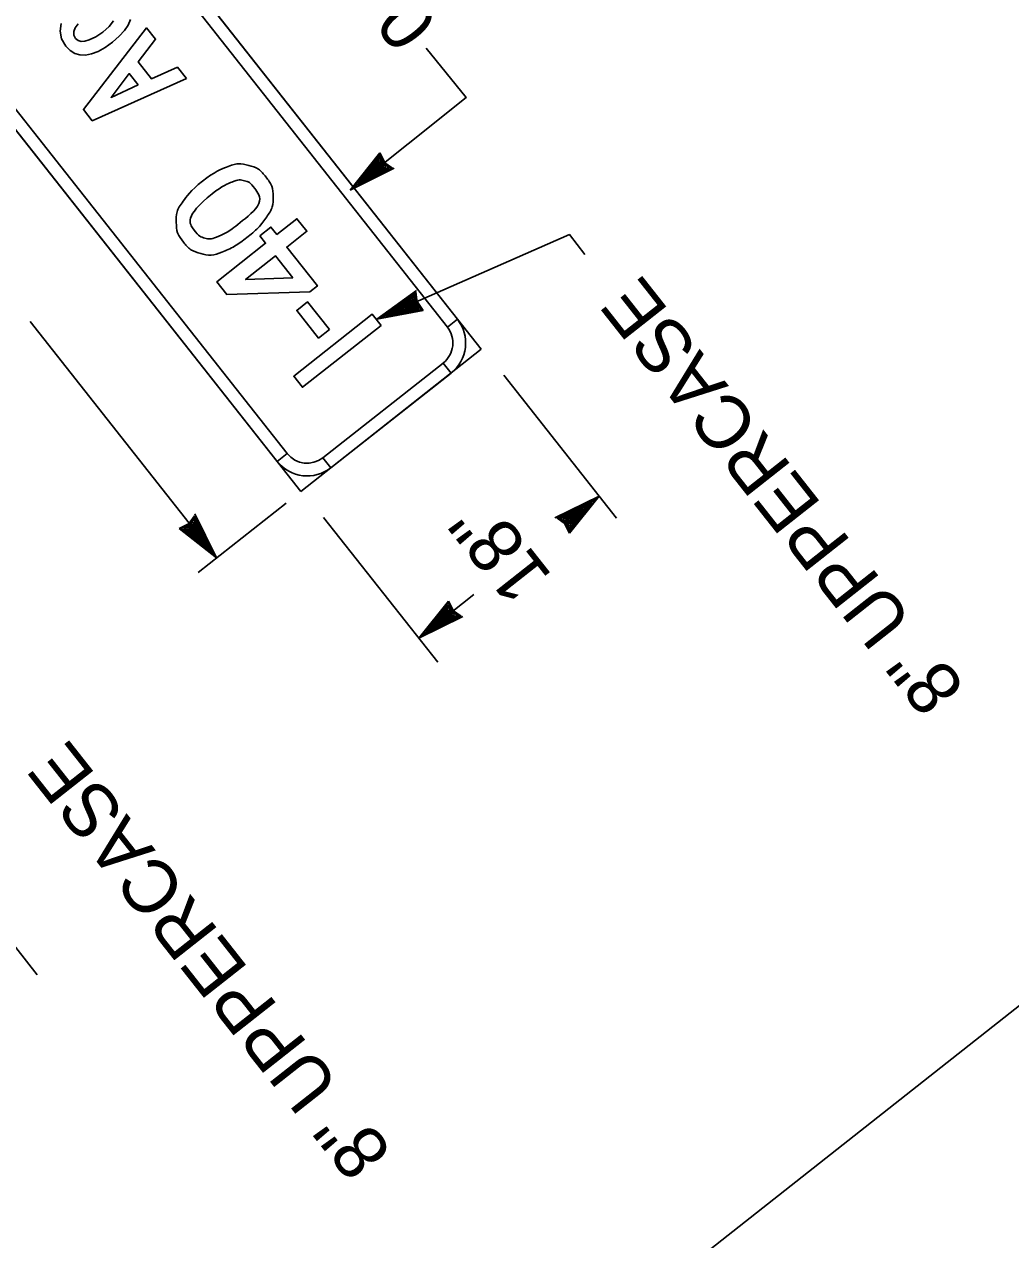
# Model space of a CAD drawing. Extents: x 672126 to 673696, y 1673540 to 1674900.
# Drawn here: x 672298.2 to 672375.5, y 1674587.2 to 1674682.5 of the extents above; entities that cross this region are included whole.
import ezdxf

# ---------------------------------------------------------------- set-up
doc = ezdxf.new("R2010")
doc.units = 0
doc.layers.add('C-ANNO-SYMB', color=7, linetype='Continuous')
doc.layers.add('Level 1', color=7, linetype='Continuous')

msp = doc.modelspace()

# ---------------------------------------------------------------- linework, layer by layer
at = {"layer": 'C-ANNO-SYMB'}
for p, q in [((672289.398, 1674713.6), (672333.973, 1674657.057)), ((672275.262, 1674702.456), (672319.838, 1674645.914)), ((672332.116, 1674659.413), (672331.331, 1674658.794)), ((672319.838, 1674645.914), (672333.973, 1674657.057)), ((672330.998, 1674655.985), (672331.617, 1674655.2)), ((672318.766, 1674648.889), (672317.98, 1674648.27)), ((672322.194, 1674647.771), (672321.575, 1674648.556))]:
    msp.add_line(p, q, dxfattribs=at)
for points in [[(672331.331, 1674658.794), (672290.47, 1674710.625), (672291.255, 1674711.244), (672332.116, 1674659.413), (672331.331, 1674658.794), (672331.331, 1674658.794)], [(672277.905, 1674700.719), (672318.766, 1674648.889), (672317.98, 1674648.27), (672277.12, 1674700.1), (672277.905, 1674700.719), (672277.905, 1674700.719)], [(672322.081, 1674658.601), (672320.367, 1674660.775), (672319.521, 1674660.108), (672321.235, 1674657.934)], [(672326.125, 1674658.937), (672325.439, 1674659.807), (672319.278, 1674654.949), (672319.963, 1674654.08)], [(672321.575, 1674648.556), (672330.998, 1674655.985), (672331.617, 1674655.2), (672322.194, 1674647.771), (672321.575, 1674648.556), (672321.575, 1674648.556)]]:
    msp.add_lwpolyline(points, close=True, dxfattribs=at)
for points in [[(672301.055, 1674682.604), (672300.962, 1674682.007), (672301.088, 1674681.405), (672301.42, 1674680.832), (672301.751, 1674680.489), (672302.116, 1674680.26), (672302.519, 1674680.137), (672302.955, 1674680.123), (672303.432, 1674680.217), (672303.94, 1674680.419), (672304.487, 1674680.731), (672305.069, 1674681.15), (672305.591, 1674681.602), (672306.002, 1674682.045), (672306.303, 1674682.481), (672306.489, 1674682.909)], [(672305.163, 1674682.816), (672304.8, 1674682.376), (672304.305, 1674681.937), (672303.764, 1674681.563), (672303.245, 1674681.312), (672302.903, 1674681.211), (672302.61, 1674681.198), (672302.373, 1674681.27), (672302.183, 1674681.433), (672302.05, 1674681.69), (672302.037, 1674681.967), (672302.146, 1674682.268), (672302.371, 1674682.588)], [(672310.87, 1674678.287), (672310.165, 1674679.181), (672308.14, 1674678.261), (672307.092, 1674679.59), (672308.445, 1674681.364), (672307.735, 1674682.264), (672302.798, 1674675.853), (672303.485, 1674674.983), (672310.87, 1674678.287)], [(672307.092, 1674677.787), (672304.96, 1674676.811), (672306.387, 1674678.682), (672307.092, 1674677.787)], [(672316.619, 1674665.954), (672317.499, 1674666.647), (672317.96, 1674666.063), (672319.531, 1674667.301), (672320.31, 1674666.313), (672318.739, 1674665.075), (672321.136, 1674662.033), (672320.546, 1674661.567), (672314.025, 1674661.359), (672313.246, 1674662.347), (672317.08, 1674665.369), (672316.619, 1674665.954)], [(672319.221, 1674662.653), (672317.859, 1674664.381), (672315.509, 1674662.528), (672319.221, 1674662.653)]]:
    msp.add_lwpolyline(points, dxfattribs=at)
for centre, radius, start, end in [((672329.76, 1674657.556), 3, 308.25039, 38.2506), ((672329.76, 1674657.556), 2, 308.25039, 38.2506), ((672320.336, 1674650.127), 2, 218.25075, 308.25039), ((672320.336, 1674650.127), 3, 218.25075, 308.25039)]:
    msp.add_arc(centre, radius, start, end, dxfattribs=at)
for points in [[(672312.123, 1674670.234), (672313.085, 1674670.992), (672314.129, 1674671.387), (672314.923, 1674671.698), (672315.757, 1674671.48), (672316.563, 1674671.259), (672317.104, 1674670.574), (672317.644, 1674669.889), (672317.664, 1674669.048), (672317.686, 1674668.193), (672317.186, 1674667.484), (672316.539, 1674666.559), (672315.603, 1674665.821), (672314.667, 1674665.083), (672313.616, 1674664.67), (672312.805, 1674664.355), (672311.99, 1674664.575), (672311.166, 1674664.792), (672310.631, 1674665.471), (672310.096, 1674666.15), (672310.076, 1674667.002), (672310.048, 1674667.865), (672310.535, 1674668.565), (672311.181, 1674669.491), (672312.123, 1674670.234)], [(672312.894, 1674669.256), (672310.638, 1674667.478), (672311.605, 1674666.252), (672311.887, 1674665.894), (672312.307, 1674665.781), (672312.727, 1674665.669), (672313.15, 1674665.83), (672314.034, 1674666.169), (672314.832, 1674666.799), (672317.088, 1674668.577), (672316.117, 1674669.809), (672315.834, 1674670.168), (672315.42, 1674670.279), (672315.006, 1674670.391), (672314.582, 1674670.23), (672313.693, 1674669.886), (672312.894, 1674669.256)]]:
    msp.add_open_spline(points, degree=3, dxfattribs=at)
at = {"layer": 'Level 1'}
for p, q in [((672525.22, 1674723.119), (672265.685, 1674518.515)), ((672323.7, 1674669.545), (672326.02, 1674672.456)), ((672323.918, 1674669.782), (672326.002, 1674672.307)), ((672326.002, 1674672.307), (672326.343, 1674671.742)), ((672326.02, 1674672.456), (672326.412, 1674671.696)), ((672324.269, 1674670.057), (672325.999, 1674672.139)), ((672324.488, 1674670.157), (672326.042, 1674671.873)), ((672324.559, 1674670.281), (672326.001, 1674672.007)), ((672324.993, 1674670.621), (672325.987, 1674671.729)), ((672326.503, 1674671.368), (672324.993, 1674670.621)), ((672325.38, 1674670.89), (672325.951, 1674671.602)), ((672326.34, 1674671.407), (672325.38, 1674670.89)), ((672326.045, 1674671.742), (672325.54, 1674670.983)), ((672325.716, 1674671.185), (672325.981, 1674671.525)), ((672326.233, 1674671.456), (672325.716, 1674671.185)), ((672325.951, 1674671.602), (672326.233, 1674671.456)), ((672325.981, 1674671.525), (672326.064, 1674671.46)), ((672325.987, 1674671.729), (672326.34, 1674671.407)), ((672325.999, 1674672.139), (672326.137, 1674671.879)), ((672326.001, 1674672.007), (672326.682, 1674671.309)), ((672326.042, 1674671.873), (672326.503, 1674671.368)), ((672326.421, 1674671.471), (672326.045, 1674671.742)), ((672326.064, 1674671.46), (672326.421, 1674671.471)), ((672326.137, 1674671.879), (672326.682, 1674671.309)), ((672326.343, 1674671.742), (672327.014, 1674671.269)), ((672326.412, 1674671.696), (672326.654, 1674671.387)), ((672326.654, 1674671.387), (672326.969, 1674671.199)), ((672327.161, 1674671.251), (672323.7, 1674669.545)), ((672326.803, 1674671.237), (672323.96, 1674669.813)), ((672326.969, 1674671.199), (672324.121, 1674669.905)), ((672326.682, 1674671.309), (672324.488, 1674670.157)), ((672326.682, 1674671.309), (672324.559, 1674670.281)), ((672325.54, 1674670.983), (672325.286, 1674670.883)), ((672327.014, 1674671.269), (672326.795, 1674671.333)), ((672326.795, 1674671.333), (672326.803, 1674671.237)), ((672328.904, 1674661.681), (672325.785, 1674659.411)), ((672328.725, 1674661.371), (672326.142, 1674659.516)), ((672328.769, 1674661.535), (672326.299, 1674659.616)), ((672328.733, 1674661.23), (672326.693, 1674659.824)), ((672328.733, 1674661.23), (672326.835, 1674659.829)), ((672328.701, 1674661.044), (672327.338, 1674660.055)), ((672328.661, 1674660.882), (672327.756, 1674660.273)), ((672328.579, 1674660.612), (672328.755, 1674660.924)), ((672328.781, 1674660.419), (672328.661, 1674660.882)), ((672328.935, 1674660.401), (672328.701, 1674661.044)), ((672328.806, 1674661.319), (672328.725, 1674661.371)), ((672328.984, 1674660.483), (672328.733, 1674661.23)), ((672329.034, 1674660.302), (672328.733, 1674661.23)), ((672328.755, 1674660.924), (672328.82, 1674660.465)), ((672328.789, 1674661.169), (672328.769, 1674661.535)), ((672328.95, 1674660.811), (672328.789, 1674661.169)), ((672328.852, 1674661.542), (672328.806, 1674661.319)), ((672328.958, 1674660.728), (672328.852, 1674661.542)), ((672325.785, 1674659.411), (672329.44, 1674660.111)), ((672326.095, 1674659.494), (672329.3, 1674660.163)), ((672326.265, 1674659.686), (672327.013, 1674660.196)), ((672326.502, 1674659.676), (672329.149, 1674660.239)), ((672327.013, 1674660.196), (672326.502, 1674659.676)), ((672326.693, 1674659.824), (672328.935, 1674660.401)), ((672326.835, 1674659.829), (672329.034, 1674660.302)), ((672327.23, 1674660.035), (672327.617, 1674660.324)), ((672327.706, 1674660.193), (672327.23, 1674660.035)), ((672327.338, 1674660.055), (672328.781, 1674660.419)), ((672327.913, 1674660.37), (672327.706, 1674660.193)), ((672327.756, 1674660.273), (672328.652, 1674660.447)), ((672328.82, 1674660.465), (672327.913, 1674660.37)), ((672328.654, 1674660.764), (672328.174, 1674660.432)), ((672328.174, 1674660.432), (672328.598, 1674660.509)), ((672328.598, 1674660.509), (672328.579, 1674660.612)), ((672328.652, 1674660.447), (672328.654, 1674660.764)), ((672329.44, 1674660.111), (672328.95, 1674660.811)), ((672329.3, 1674660.163), (672328.958, 1674660.728)), ((672329.149, 1674660.239), (672328.984, 1674660.483)), ((672313.221, 1674640.698), (672298.606, 1674659.236)), ((672326.299, 1674659.616), (672326.095, 1674659.494)), ((672326.142, 1674659.516), (672326.265, 1674659.686)), ((672335.76, 1674655.02), (672344.589, 1674643.821)), ((672318.681, 1674645.002), (672311.777, 1674639.559)), ((672339.76, 1674643.852), (672343.221, 1674645.556)), ((672339.952, 1674643.904), (672342.801, 1674645.196)), ((672340.118, 1674643.866), (672342.962, 1674645.288)), ((672340.239, 1674643.794), (672342.433, 1674644.944)), ((672340.239, 1674643.794), (672342.362, 1674644.821)), ((672342.433, 1674644.944), (672340.878, 1674643.229)), ((672343.221, 1674645.556), (672340.9, 1674642.647)), ((672343.004, 1674645.32), (672340.918, 1674642.796)), ((672342.362, 1674644.821), (672340.919, 1674643.095)), ((672342.652, 1674645.044), (672340.921, 1674642.964)), ((672342.754, 1674645.259), (672341.955, 1674644.834)), ((672341.955, 1674644.834), (672342.652, 1674645.044)), ((672342.962, 1674645.288), (672342.754, 1674645.259)), ((672342.801, 1674645.196), (672343.004, 1674645.32)), ((672311.027, 1674643.342), (672311.5, 1674644.012)), ((672311.382, 1674643.653), (672311.57, 1674643.967)), ((672311.5, 1674644.012), (672311.436, 1674643.793)), ((672311.436, 1674643.793), (672311.532, 1674643.801)), ((672311.518, 1674644.159), (672313.221, 1674640.698)), ((672311.532, 1674643.801), (672312.954, 1674640.957)), ((672311.57, 1674643.967), (672312.862, 1674641.118)), ((672321.624, 1674643.876), (672330.58, 1674632.516)), ((672340.577, 1674643.361), (672339.907, 1674643.834)), ((672339.907, 1674643.834), (672340.126, 1674643.771)), ((672340.266, 1674643.716), (672339.952, 1674643.904)), ((672340.126, 1674643.771), (672340.118, 1674643.866)), ((672340.783, 1674643.224), (672340.239, 1674643.794)), ((672340.919, 1674643.095), (672340.239, 1674643.794)), ((672340.508, 1674643.407), (672340.266, 1674643.716)), ((672340.418, 1674643.735), (672341.928, 1674644.481)), ((672340.878, 1674643.229), (672340.418, 1674643.735)), ((672340.58, 1674643.696), (672341.541, 1674644.212)), ((672340.688, 1674643.646), (672341.205, 1674643.917)), ((672340.875, 1674643.361), (672341.381, 1674644.119)), ((672341.928, 1674644.481), (672340.934, 1674643.373)), ((672341.205, 1674643.917), (672340.939, 1674643.577)), ((672341.541, 1674644.212), (672340.969, 1674643.501)), ((672341.381, 1674644.119), (672341.634, 1674644.219)), ((672341.996, 1674644.567), (672341.56, 1674644.359)), ((672341.634, 1674644.219), (672341.996, 1674644.567)), ((672310.313, 1674643.019), (672311.072, 1674643.411)), ((672313.221, 1674640.698), (672310.313, 1674643.019)), ((672310.461, 1674643.001), (672311.027, 1674643.342)), ((672312.985, 1674640.915), (672310.461, 1674643.001)), ((672310.63, 1674642.998), (672310.89, 1674643.136)), ((672312.71, 1674641.267), (672310.63, 1674642.998)), ((672310.761, 1674643), (672311.46, 1674643.68)), ((672312.486, 1674641.557), (672310.761, 1674643)), ((672310.89, 1674643.136), (672311.46, 1674643.68)), ((672310.895, 1674643.041), (672311.401, 1674643.501)), ((672312.61, 1674641.486), (672310.895, 1674643.041)), ((672311.298, 1674643.42), (672311.027, 1674643.044)), ((672311.027, 1674643.044), (672311.785, 1674642.538)), ((672311.039, 1674642.985), (672311.361, 1674643.339)), ((672312.147, 1674641.991), (672311.039, 1674642.985)), ((672311.072, 1674643.411), (672311.382, 1674643.653)), ((672311.166, 1674642.95), (672311.312, 1674643.231)), ((672311.878, 1674642.378), (672311.166, 1674642.95)), ((672311.243, 1674642.98), (672311.308, 1674643.062)), ((672311.583, 1674642.714), (672311.243, 1674642.98)), ((672311.308, 1674643.062), (672311.298, 1674643.42)), ((672311.312, 1674643.231), (672311.583, 1674642.714)), ((672311.361, 1674643.339), (672311.878, 1674642.378)), ((672311.401, 1674643.501), (672312.147, 1674641.991)), ((672311.46, 1674643.68), (672312.486, 1674641.557)), ((672311.46, 1674643.68), (672312.61, 1674641.486)), ((672340.857, 1674643.643), (672340.499, 1674643.632)), ((672340.499, 1674643.632), (672340.875, 1674643.361)), ((672340.9, 1674642.647), (672340.508, 1674643.407)), ((672340.918, 1674642.796), (672340.577, 1674643.361)), ((672340.934, 1674643.373), (672340.58, 1674643.696)), ((672340.969, 1674643.501), (672340.688, 1674643.646)), ((672340.921, 1674642.964), (672340.783, 1674643.224)), ((672340.939, 1674643.577), (672340.857, 1674643.643)), ((672311.785, 1674642.538), (672311.885, 1674642.285)), ((672311.885, 1674642.285), (672312.233, 1674641.923)), ((672312.233, 1674641.923), (672312.025, 1674642.359)), ((672312.924, 1674641.165), (672312.499, 1674641.964)), ((672312.499, 1674641.964), (672312.71, 1674641.267)), ((672312.862, 1674641.118), (672312.985, 1674640.915)), ((672312.954, 1674640.957), (672312.924, 1674641.165)), ((672329.086, 1674634.412), (672333.411, 1674637.822)), ((672329.086, 1674634.412), (672331.407, 1674637.321)), ((672329.304, 1674634.648), (672331.389, 1674637.172)), ((672331.389, 1674637.172), (672331.73, 1674636.607)), ((672331.407, 1674637.321), (672331.799, 1674636.561)), ((672332.547, 1674636.115), (672329.086, 1674634.412)), ((672332.19, 1674636.101), (672329.346, 1674634.68)), ((672329.655, 1674634.923), (672331.386, 1674637.004)), ((672329.874, 1674635.023), (672331.429, 1674636.738)), ((672332.068, 1674636.174), (672329.874, 1674635.023)), ((672329.945, 1674635.147), (672331.388, 1674636.872)), ((672332.068, 1674636.174), (672329.945, 1674635.147)), ((672330.379, 1674635.486), (672331.374, 1674636.594)), ((672331.889, 1674636.232), (672330.379, 1674635.486)), ((672330.767, 1674635.755), (672331.338, 1674636.467)), ((672331.727, 1674636.272), (672330.767, 1674635.755)), ((672331.432, 1674636.607), (672330.926, 1674635.849)), ((672331.102, 1674636.05), (672331.368, 1674636.39)), ((672331.619, 1674636.321), (672331.102, 1674636.05)), ((672331.338, 1674636.467), (672331.619, 1674636.321)), ((672331.368, 1674636.39), (672331.45, 1674636.325)), ((672331.374, 1674636.594), (672331.727, 1674636.272)), ((672331.386, 1674637.004), (672331.524, 1674636.743)), ((672331.388, 1674636.872), (672332.068, 1674636.174)), ((672331.429, 1674636.738), (672331.889, 1674636.232)), ((672331.808, 1674636.336), (672331.432, 1674636.607)), ((672331.45, 1674636.325), (672331.808, 1674636.336)), ((672331.524, 1674636.743), (672332.068, 1674636.174)), ((672331.73, 1674636.607), (672332.4, 1674636.134)), ((672331.799, 1674636.561), (672332.041, 1674636.251)), ((672332.041, 1674636.251), (672332.355, 1674636.063)), ((672332.4, 1674636.134), (672332.181, 1674636.197)), ((672332.181, 1674636.197), (672332.19, 1674636.101)), ((672332.355, 1674636.063), (672329.506, 1674634.771)), ((672330.673, 1674635.748), (672330.311, 1674635.4)), ((672330.311, 1674635.4), (672330.747, 1674635.608)), ((672330.926, 1674635.849), (672330.673, 1674635.748)), ((672329.506, 1674634.771), (672329.304, 1674634.648)), ((672329.346, 1674634.68), (672329.553, 1674634.709)), ((672329.553, 1674634.709), (672330.352, 1674635.134)), ((672330.352, 1674635.134), (672329.655, 1674634.923)), ((672290.346, 1674619.218), (672299.175, 1674608.019))]:
    msp.add_line(p, q, dxfattribs=at)
for points in [[(672323.7, 1674669.545), (672332.813, 1674676.806), (672329.675, 1674680.662)], [(672325.785, 1674659.411), (672340.893, 1674666.048), (672342.115, 1674664.497)]]:
    msp.add_lwpolyline(points, dxfattribs=at)

# ---------------------------------------------------------------- texts
for s, p in [('0.75" WHITE ', (672330.746, 1674682.674)), ('8" UPPERCASE', (672372.036, 1674630.549)), ('18"', (672339.63, 1674639.25)), ('8" UPPERCASE', (672327.105, 1674594.135))]:
    msp.add_text(s, height=4.2, rotation=128.25054, dxfattribs=at).set_placement(p)

doc.saveas('drawing.dxf')
